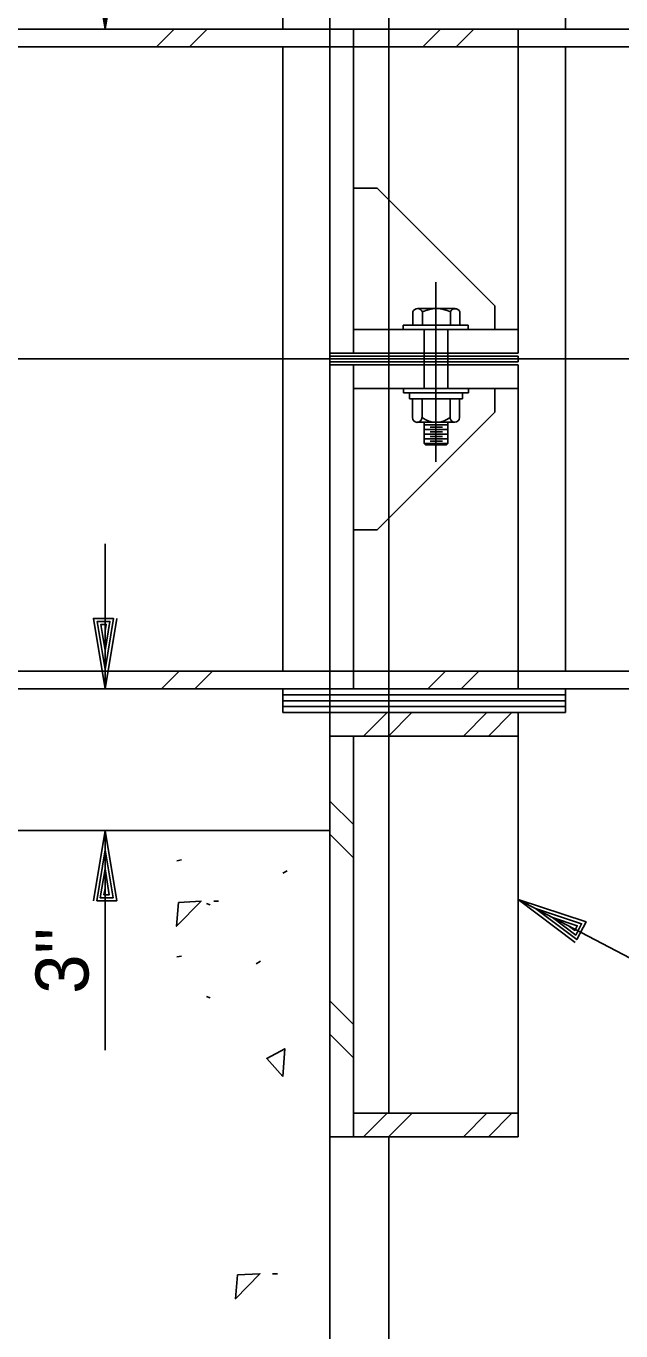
# Model space of a CAD drawing. Extents: x 22369.6 to 22389.4, y 22369.6 to 22386.
# Drawn here: x 22377.944 to 22378.471, y 22377.463 to 22378.617 of the extents above; entities that cross this region are included whole.
import ezdxf

# ---------------------------------------------------------------- set-up
doc = ezdxf.new("R2010")
doc.units = 0
for name, color, linetype in [('Level 1', 7, 'Continuous'), ('Level 2', 7, 'Continuous'), ('Level 3', 7, 'Continuous'), ('Level 4', 7, 'Continuous'), ('Level 44', 7, 'Continuous'), ('Level 50', 7, 'Continuous'), ('Level 7', 7, 'Continuous')]:
    doc.layers.add(name, color=color, linetype=linetype)

msp = doc.modelspace()

# ---------------------------------------------------------------- linework, layer by layer
at = {"layer": 'Level 1'}
for p, q in [((22378.0144, 22378.6139), (22378.0144, 22378.9056)), ((22378.0598, 22378.5983), (22378.0754, 22378.6139)), ((22378.0892, 22378.5983), (22378.1048, 22378.6139)), ((22378.2955, 22378.5983), (22378.3111, 22378.6139)), ((22378.3249, 22378.5983), (22378.3406, 22378.6139)), ((22378.3071, 22378.2315), (22378.3071, 22378.3901)), ((22378.2866, 22378.364), (22378.2866, 22378.3522)), ((22378.2909, 22378.3668), (22378.3241, 22378.3668)), ((22378.2952, 22378.3641), (22378.2952, 22378.3522)), ((22378.3199, 22378.364), (22378.3199, 22378.3522)), ((22378.3283, 22378.364), (22378.3283, 22378.3522)), ((22378.3355, 22378.3522), (22378.2782, 22378.3522)), ((22378.2782, 22378.3483), (22378.2782, 22378.3522)), ((22378.2967, 22378.2962), (22378.2967, 22378.3483)), ((22378.3176, 22378.2962), (22378.3176, 22378.3483)), ((22378.3355, 22378.3483), (22378.3355, 22378.3522)), ((22376.6793, 22378.3223), (22379.57, 22378.3223)), ((22378.2133, 22378.3249), (22378.38, 22378.3249)), ((22378.38, 22378.3197), (22378.38, 22378.3249)), ((22378.2133, 22378.3197), (22378.38, 22378.3197)), ((22378.2785, 22378.2923), (22378.2785, 22378.2962)), ((22378.2785, 22378.2923), (22378.3358, 22378.2923)), ((22378.2837, 22378.2871), (22378.2837, 22378.2923)), ((22378.2837, 22378.2871), (22378.3306, 22378.2871)), ((22378.2863, 22378.2871), (22378.2863, 22378.2705)), ((22378.2949, 22378.2871), (22378.2949, 22378.2705)), ((22378.3196, 22378.2871), (22378.3196, 22378.2705)), ((22378.328, 22378.2871), (22378.328, 22378.2705)), ((22378.3306, 22378.2871), (22378.3306, 22378.2923)), ((22378.3358, 22378.2923), (22378.3358, 22378.2962)), ((22378.2906, 22378.2663), (22378.3238, 22378.2663)), ((22378.2967, 22378.2663), (22378.2967, 22378.2475)), ((22378.2967, 22378.2642), (22378.3176, 22378.2642)), ((22378.3176, 22378.2663), (22378.3176, 22378.2476)), ((22378.2967, 22378.26), (22378.3176, 22378.26)), ((22378.2967, 22378.2558), (22378.3176, 22378.2558)), ((22378.302, 22378.2621), (22378.3129, 22378.2621)), ((22378.302, 22378.2579), (22378.3129, 22378.2579)), ((22378.302, 22378.2538), (22378.3129, 22378.2538)), ((22378.2967, 22378.2517), (22378.3176, 22378.2517)), ((22378.2967, 22378.2475), (22378.2978, 22378.2465)), ((22378.2967, 22378.2475), (22378.3176, 22378.2475)), ((22378.2978, 22378.2465), (22378.3165, 22378.2465)), ((22378.302, 22378.2496), (22378.3129, 22378.2496)), ((22378.3176, 22378.2476), (22378.3165, 22378.2465)), ((22378.0144, 22378.0306), (22378.0144, 22378.159)), ((22378.0642, 22378.0306), (22378.0798, 22378.0462)), ((22378.0937, 22378.0306), (22378.1093, 22378.0462)), ((22378.2999, 22378.0306), (22378.3155, 22378.0462)), ((22378.3293, 22378.0306), (22378.345, 22378.0462)), ((22378.4216, 22378.0254), (22378.1716, 22378.0254)), ((22378.4216, 22378.0202), (22378.1716, 22378.0202)), ((22378.4216, 22378.015), (22378.1716, 22378.015)), ((22378.2431, 22377.9889), (22378.2639, 22378.0098)), ((22378.2651, 22377.9889), (22378.2859, 22378.0098)), ((22378.3314, 22377.9889), (22378.3522, 22378.0098)), ((22378.3535, 22377.9889), (22378.3743, 22378.0098)), ((22378.2341, 22377.9107), (22378.2133, 22377.9315)), ((22378.0144, 22377.7113), (22378.0144, 22377.9056)), ((22378.2341, 22377.8812), (22378.2133, 22377.9021)), ((22378.2341, 22377.7339), (22378.2133, 22377.7548)), ((22378.2341, 22377.7045), (22378.2133, 22377.7253)), ((22378.243, 22377.6348), (22378.2639, 22377.6556)), ((22378.2651, 22377.6348), (22378.286, 22377.6556)), ((22378.3314, 22377.6348), (22378.3522, 22377.6556)), ((22378.3535, 22377.6348), (22378.3743, 22377.6556))]:
    msp.add_line(p, q, dxfattribs=at)
for centre, radius, start, end in [((22378.2909, 22378.3621), 0.00469, 24.0009, 156.8325), ((22378.3075, 22378.3383), 0.0285, 64.116, 115.4481), ((22378.3241, 22378.3622), 0.00456, 22.8005, 157.625), ((22378.2905, 22378.2705), 0.00422, 180.5659, 359.4341), ((22378.3072, 22378.2866), 0.0203, 232.4343, 307.5657), ((22378.3238, 22378.2705), 0.00421, 180.4975, 359.5025)]:
    msp.add_arc(centre, radius, start, end, dxfattribs=at)
at = {"layer": 'Level 2'}
for p, q in [((22378.1716, 22378.6139), (22378.1716, 22378.6348)), ((22378.4216, 22378.6139), (22378.4216, 22378.6348)), ((22377.0362, 22378.6139), (22378.7654, 22378.6139)), ((22378.0144, 22378.6139), (22378.0144, 22378.6139)), ((22378.2133, 22378.3275), (22378.2133, 22378.6139)), ((22378.2341, 22378.3275), (22378.2341, 22378.6139)), ((22378.38, 22378.3275), (22378.38, 22378.6139)), ((22377.0175, 22378.5983), (22378.7466, 22378.5983)), ((22378.1716, 22378.0462), (22378.1716, 22378.5983)), ((22378.4216, 22378.0462), (22378.4216, 22378.5983)), ((22378.2551, 22378.4733), (22378.2342, 22378.4733)), ((22378.3592, 22378.3692), (22378.2551, 22378.4733)), ((22378.3592, 22378.3483), (22378.3592, 22378.3692)), ((22378.38, 22378.3483), (22378.2341, 22378.3483)), ((22378.38, 22378.3275), (22378.2133, 22378.3275)), ((22378.38, 22378.3171), (22378.2133, 22378.3171)), ((22378.2133, 22378.0306), (22378.2133, 22378.3171)), ((22378.2341, 22378.0306), (22378.2341, 22378.3171)), ((22378.38, 22378.0306), (22378.38, 22378.3171)), ((22378.38, 22378.2962), (22378.2341, 22378.2962)), ((22378.3592, 22378.2754), (22378.3592, 22378.2962)), ((22378.3592, 22378.2754), (22378.2551, 22378.1712)), ((22378.2551, 22378.1712), (22378.2342, 22378.1712)), ((22377.055, 22378.0462), (22378.7841, 22378.0462)), ((22378.0144, 22378.0479), (22378.0144, 22378.0479)), ((22377.0362, 22378.0306), (22378.7654, 22378.0306)), ((22378.0144, 22378.0306), (22378.0144, 22378.0306)), ((22378.1716, 22378.0098), (22378.1716, 22378.0306)), ((22378.4216, 22378.0098), (22378.4216, 22378.0306)), ((22378.4216, 22378.0098), (22378.1716, 22378.0098)), ((22378.2133, 22377.6348), (22378.2133, 22378.0098)), ((22378.38, 22377.6348), (22378.38, 22378.0098)), ((22378.38, 22377.9889), (22378.2133, 22377.9889)), ((22378.2341, 22377.6348), (22378.2341, 22377.9889)), ((22378.0144, 22377.9056), (22378.0144, 22377.9056)), ((22378.0144, 22377.8883), (22378.0144, 22377.8883)), ((22378.38, 22377.8445), (22378.38, 22377.8445)), ((22378.3953, 22377.8365), (22378.3953, 22377.8365)), ((22378.38, 22377.6556), (22378.2341, 22377.6556)), ((22378.38, 22377.6348), (22378.2133, 22377.6348))]:
    msp.add_line(p, q, dxfattribs=at)
for points in [[(22378.0247, 22378.6763), (22378.0144, 22378.6139), (22378.0041, 22378.6763), (22378.0217, 22378.6763), (22378.0144, 22378.6313), (22378.0074, 22378.6736), (22378.0187, 22378.6736), (22378.0144, 22378.6479), (22378.0107, 22378.6709), (22378.0154, 22378.6709), (22378.0144, 22378.6653)], [(22378.0247, 22378.0929), (22378.0144, 22378.0306), (22378.0041, 22378.0929), (22378.0217, 22378.0929), (22378.0144, 22378.0479), (22378.0074, 22378.0903), (22378.0187, 22378.0903), (22378.0144, 22378.0646), (22378.0107, 22378.0876), (22378.0154, 22378.0876), (22378.0144, 22378.0819)], [(22378.0041, 22377.8433), (22378.0144, 22377.9056), (22378.0247, 22377.8433), (22378.0071, 22377.8433), (22378.0144, 22377.8883), (22378.0214, 22377.8459), (22378.0101, 22377.8459), (22378.0144, 22377.8716), (22378.0181, 22377.8486), (22378.0134, 22377.8486), (22378.0144, 22377.8543)], [(22378.5958, 22377.7699), (22378.5222, 22377.7699), (22378.38, 22377.8445)], [(22378.4303, 22377.8064), (22378.38, 22377.8445), (22378.44, 22377.8247), (22378.4317, 22377.8091), (22378.3953, 22377.8365), (22378.436, 22377.823), (22378.4308, 22377.813), (22378.4101, 22377.8287), (22378.4321, 22377.8213), (22378.43, 22377.8172), (22378.4254, 22377.8207)]]:
    msp.add_lwpolyline(points, dxfattribs=at)
at = {"layer": 'Level 3'}
msp.add_line((22378.2551, 22378.1712), (22378.2551, 22378.1712), dxfattribs=at)
at = {"layer": 'Level 44'}
for p, q in [((22378.0778, 22377.8787), (22378.0821, 22377.8794)), ((22378.1716, 22377.8677), (22378.1754, 22377.8699)), ((22378.104, 22377.8409), (22378.1072, 22377.8397)), ((22378.1105, 22377.843), (22378.1148, 22377.843)), ((22378.0778, 22377.7937), (22378.0821, 22377.7944)), ((22378.1481, 22377.7876), (22378.1519, 22377.7899)), ((22378.104, 22377.7587), (22378.1072, 22377.7574)), ((22378.1626, 22377.5137), (22378.1669, 22377.5137))]:
    msp.add_line(p, q, dxfattribs=at)
for points in [[(22378.0793, 22377.8419), (22378.0993, 22377.843), (22378.0776, 22377.8208)], [(22378.1716, 22377.688), (22378.1574, 22377.704), (22378.1733, 22377.7125)], [(22378.1314, 22377.5126), (22378.1514, 22377.5137), (22378.1297, 22377.4915)]]:
    msp.add_lwpolyline(points, close=True, dxfattribs=at)
at = {"layer": 'Level 50'}
msp.add_line((22378.328, 22378.2705), (22378.328, 22378.2705), dxfattribs=at)
at = {"layer": 'Level 7'}
for p, q in [((22378.2133, 22378.6139), (22378.2133, 22380.0223)), ((22378.2654, 22377.6556), (22378.2654, 22378.9889)), ((22378.2133, 22378.0462), (22378.2133, 22378.5983)), ((22378.2133, 22376.3207), (22378.2133, 22378.0306)), ((22377.7133, 22377.9056), (22378.2133, 22377.9056)), ((22378.2654, 22376.4978), (22378.2654, 22377.6348))]:
    msp.add_line(p, q, dxfattribs=at)

# ---------------------------------------------------------------- texts
at = {"layer": 'Level 4'}
msp.add_text("3''", height=0.04688, rotation=90, dxfattribs=at).set_placement((22377.9997, 22377.7611))

doc.saveas('drawing.dxf')
